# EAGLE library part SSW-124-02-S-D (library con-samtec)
THROUGH-HOLE .025" SQ POST SOCKET Source: Samtec SSW.pdf
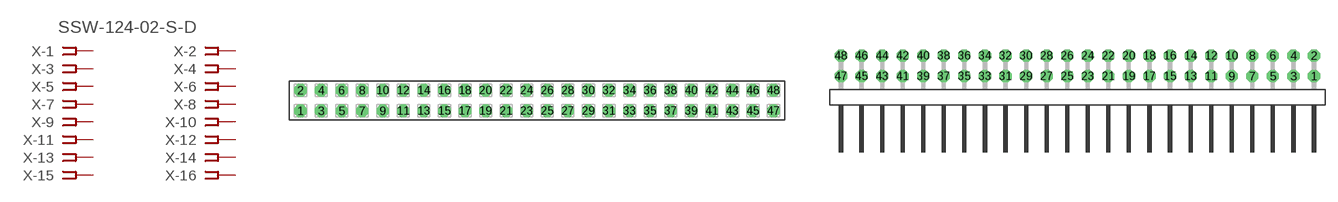
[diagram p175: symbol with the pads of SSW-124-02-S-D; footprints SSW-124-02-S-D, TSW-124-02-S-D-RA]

Designator prefix X; gates -1=FPINV -2=FPIN -3=FPIN -4=FPIN -5=FPIN -6=FPIN -7=FPIN -8=FPIN -9=FPIN -10=FPIN -11=FPIN -12=FPIN -13=FPIN -14=FPIN -15=FPIN -16=FPIN -17=FPIN -18=FPIN -19=FPIN -20=FPIN -21=FPIN -22=FPIN -23=FPIN -24=FPIN -25=FPIN -26=FPIN -27=FPIN -28=FPIN -29=FPIN -30=FPIN -31=FPIN -32=FPIN -33=FPIN -34=FPIN -35=FPIN -36=FPIN -37=FPIN -38=FPIN -39=FPIN -40=FPIN -41=FPIN -42=FPIN -43=FPIN -44=FPIN -45=FPIN -46=FPIN -47=FPIN -48=FPIN

## SSW-124-02-S-D (MPN: SSW-124-02-S-D; OC_FARNELL: unknown; OC_NEWARK: 11P9707)  [SSW-124-02-S-D]
1  -1:1  pas
2  -2:1  pas
3  -3:1  pas
4  -4:1  pas
5  -5:1  pas
6  -6:1  pas
7  -7:1  pas
8  -8:1  pas
9  -9:1  pas
10  -10:1  pas
11  -11:1  pas
12  -12:1  pas
13  -13:1  pas
14  -14:1  pas
15  -15:1  pas
16  -16:1  pas
17  -17:1  pas
18  -18:1  pas
19  -19:1  pas
20  -20:1  pas
21  -21:1  pas
22  -22:1  pas
23  -23:1  pas
24  -24:1  pas
25  -25:1  pas
26  -26:1  pas
27  -27:1  pas
28  -28:1  pas
29  -29:1  pas
30  -30:1  pas
31  -31:1  pas
32  -32:1  pas
33  -33:1  pas
34  -34:1  pas
35  -35:1  pas
36  -36:1  pas
37  -37:1  pas
38  -38:1  pas
39  -39:1  pas
40  -40:1  pas
41  -41:1  pas
42  -42:1  pas
43  -43:1  pas
44  -44:1  pas
45  -45:1  pas
46  -46:1  pas
47  -47:1  pas
48  -48:1  pas

## SSW-124-02-S-D-RA (MPN: SSW-124-02-S-D-RA; OC_FARNELL: unknown; OC_NEWARK: 11P9708)  [TSW-124-02-S-D-RA]
Pads as for SSW-124-02-S-D

## Footprint SSW-124-02-S-D (pad centres in mm)
THROUGH-HOLE .025" SQ POST SOCKET Source: Samtec SSW.pdf
drill 1 pad 1.5 octagon: 1 -29.21,-1.27; 2 -29.21,1.27; 3 -26.67,-1.27; 4 -26.67,1.27; 5 -24.13,-1.27; 6 -24.13,1.27; 7 -21.59,-1.27; 8 -21.59,1.27; 9 -19.05,-1.27; 10 -19.05,1.27; 11 -16.51,-1.27; 12 -16.51,1.27; 13 -13.97,-1.27; 14 -13.97,1.27; 15 -11.43,-1.27; 16 -11.43,1.27; 17 -8.89,-1.27; 18 -8.89,1.27; 19 -6.35,-1.27; 20 -6.35,1.27; 21 -3.81,-1.27; 22 -3.81,1.27; 23 -1.27,-1.27; 24 -1.27,1.27; 25 1.27,-1.27; 26 1.27,1.27; 27 3.81,-1.27; 28 3.81,1.27; 29 6.35,-1.27; 30 6.35,1.27; 31 8.89,-1.27; 32 8.89,1.27; 33 11.43,-1.27; 34 11.43,1.27; 35 13.97,-1.27; 36 13.97,1.27; 37 16.51,-1.27; 38 16.51,1.27; 39 19.05,-1.27; 40 19.05,1.27; 41 21.59,-1.27; 42 21.59,1.27; 43 24.13,-1.27; 44 24.13,1.27; 45 26.67,-1.27; 46 26.67,1.27; 47 29.21,-1.27; 48 29.21,1.27

## Footprint TSW-124-02-S-D-RA (pad centres in mm)
THROUGH-HOLE .025" SQ POST HEADER Source: Samtec TSW.pdf
drill 1 pad 1.5 octagon: 1 29.21,1.524; 2 29.21,4.064; 3 26.67,1.524; 4 26.67,4.064; 5 24.13,1.524; 6 24.13,4.064; 7 21.59,1.524; 8 21.59,4.064; 9 19.05,1.524; 10 19.05,4.064; 11 16.51,1.524; 12 16.51,4.064; 13 13.97,1.524; 14 13.97,4.064; 15 11.43,1.524; 16 11.43,4.064; 17 8.89,1.524; 18 8.89,4.064; 19 6.35,1.524; 20 6.35,4.064; 21 3.81,1.524; 22 3.81,4.064; 23 1.27,1.524; 24 1.27,4.064; 25 -1.27,1.524; 26 -1.27,4.064; 27 -3.81,1.524; 28 -3.81,4.064; 29 -6.35,1.524; 30 -6.35,4.064; 31 -8.89,1.524; 32 -8.89,4.064; 33 -11.43,1.524; 34 -11.43,4.064; 35 -13.97,1.524; 36 -13.97,4.064; 37 -16.51,1.524; 38 -16.51,4.064; 39 -19.05,1.524; 40 -19.05,4.064; 41 -21.59,1.524; 42 -21.59,4.064; 43 -24.13,1.524; 44 -24.13,4.064; 45 -26.67,1.524; 46 -26.67,4.064; 47 -29.21,1.524; 48 -29.21,4.064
